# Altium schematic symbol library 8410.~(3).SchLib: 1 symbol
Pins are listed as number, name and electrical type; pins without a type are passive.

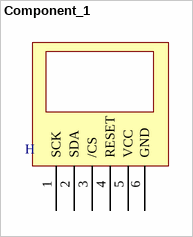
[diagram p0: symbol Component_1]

## Component_1
designator H  (value not drawn)
pins: 1 SCK, 2 SDA, 3 /CS, 4 RESET, 5 VCC, 6 GND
